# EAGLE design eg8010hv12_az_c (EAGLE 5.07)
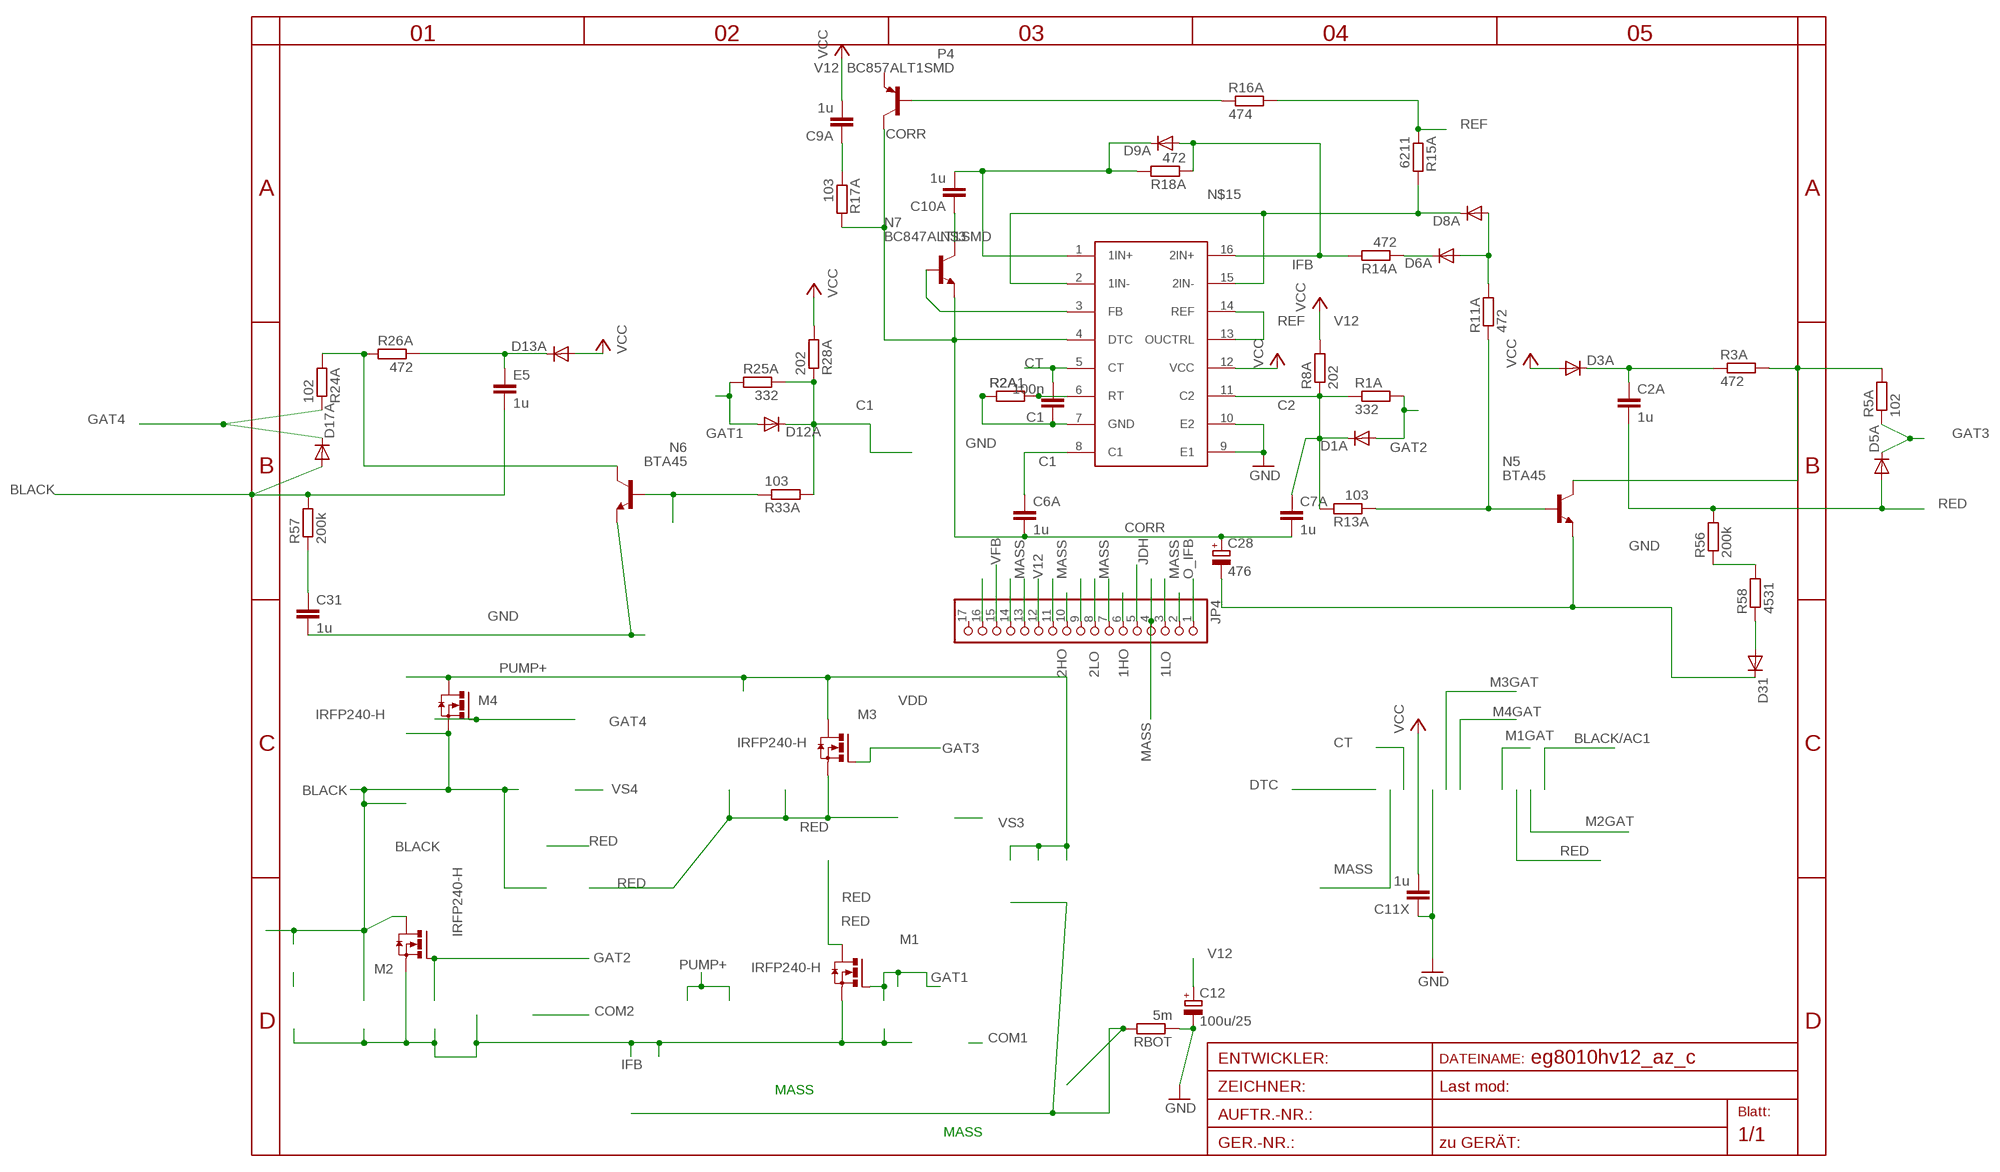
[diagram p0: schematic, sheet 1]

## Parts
C1  100n  C-EUC0805  [C0805]
C2A  1u  C-EUC1206  [C1206]
C6A  1u  C-EUC0805  [C0805]
C7A  1u  C-EUC0805  [C0805]
C9A  1u  C-EUC0805  [C0805]
C10A  1u  C-EUC1206  [C1206]
C11X  1u  C-EUC1206  [C1206]
C12  100u/25  CPOL-EUD  [PANASONIC_D]
C28  476  CPOL-EUD  [PANASONIC_D]
C31  1u  C-EUC1206  [C1206]
D1A  DIODE-MINIMELF  [MINIMELF]
D3A  DIODE-SMA-DO214  [SMA-DO214AC]
D5A  DIODE-MINIMELF  [MINIMELF]
D6A  DIODE-MINIMELF  [MINIMELF]
D8A  DIODE-MINIMELF  [MINIMELF]
D9A  DIODE-MINIMELF  [MINIMELF]
D12A  DIODE-MINIMELF  [MINIMELF]
D13A  DIODE-SMA-DO214  [SMA-DO214AC]
D17A  DIODE-MINIMELF  [MINIMELF]
D31  DIODE-MINIMELF  [MINIMELF]
E5  1u  C-EUC1206  [C1206]
JP4  PINHD-1X17  [1X17]
M1  IRFP240-H  [TO247BH]
M2  IRFP240-H  [TO247BH]
M3  IRFP240-H  [TO247BH]
M4  IRFP240-H  [TO247BH]
N5  BTA45  SMBTA45HV  [SOT23HV]
N6  BTA45  SMBTA45HV  [SOT23HV]
N7  BC847ALT1SMD  [SOT23]
P4  BC857ALT1SMD  [SOT23-BEC]
R1A  332  R-EU_R0805  [R0805]
R2A  R-EU_R0805  [R0805]
R2A1  R-EU_R0805  [R0805]
R3A  472  R-EU_R0805  [R0805]
R5A  102  R-EU_R1206  [R1206]
R8A  202  R-EU_R0805  [R0805]
R11A  472  R-EU_R0805  [R0805]
R13A  103  R-EU_R0805  [R0805]
R14A  472  R-EU_R0805  [R0805]
R15A  6211  R-EU_R1206  [R1206]
R16A  474  R-EU_R1206  [R1206]
R17A  103  R-EU_R1206  [R1206]
R18A  472  R-EU_R0805  [R0805]
R24A  102  R-EU_R1206  [R1206]
R25A  332  R-EU_R0805  [R0805]
R26A  472  R-EU_R0805  [R0805]
R28A  202  R-EU_R0805  [R0805]
R33A  103  R-EU_R0805  [R0805]
R56  200k  R-EU_R0805  [R0805]
R57  200k  R-EU_R0805  [R0805]
R58  4531  R-EU_R0805  [R0805]
RBOT  5m  R-EU_0204/7  [0204/7]
U$5  AZ7500SO16  [SO16]

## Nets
1HO: JP4.6
1LO: JP4.3
2HO: JP4.10
2LO: JP4.8
BLACK: D17A.A E5.2 M2.D M4.S R57.2
C1: C6A.1 D12A.C R25A.1 R28A.1 R33A.2 U$5.8(C1)
C2: C7A.1 D1A.C R1A.1 R8A.1 R13A.2 U$5.11(C2)
CORR: C6A.2 C7A.2 C28.+ N7.2(E) P4.C R17A.2 U$5.4(DTC)
CT: C1.2 U$5.5(CT)
DFG1: JP4.9
GAT1: D12A.A M1.G R25A.2
GAT2: D1A.A M2.G R1A.2
GAT3: D5A.C M3.G R5A.1
GAT4: D17A.C M4.G R24A.1
GND: C1.1 C11X.1 C12.- C28.- C31.2 D31.C N5.2(E) N6.2(E) R2A1.1 R2A.1 RBOT.1 U$5.7(GND) U$5.9(E1) U$5.10(E2)
IFB: D9A.A M1.S M2.S R14A.2 R18A.1 U$5.16(2IN+)
JDH: JP4.5
MASS: JP4.2 JP4.4 JP4.7 JP4.11 JP4.13 RBOT.2
N$3: C10A.2 D9A.C R18A.2 U$5.1(1IN+)
N$4: C2A.1 D3A.K(C) R3A.1
N$5: N5.3(C) R3A.2 R5A.2
N$11: N5.1(B) R11A.1 R13A.1
N$13: D6A.A D8A.A R11A.2
N$15: D8A.C R15A.2 U$5.2(1IN-) U$5.15(2IN-)
N$36: D6A.C R14A.1
N$37: P4.B R16A.1
N$38: R2A1.2 R2A.2 U$5.6(RT)
N$39: C9A.1 R17A.1
N$40: N7.1(B) U$5.3(FB)
N$41: C10A.1 N7.3(C)
N$42: D13A.K(C) E5.1 R26A.1
N$43: N6.3(C) R24A.2 R26A.2
N$44: N6.1(B) R33A.1
N$45: C31.1 R57.1
N$46: R56.1 R58.2
N$47: D31.A R58.1
O_IFB: JP4.1
PUMP+: M3.D M4.D
RED: C2A.2 D5A.A M1.D M3.S R56.2
REF: R15A.1 R16A.2 U$5.13(OUCTRL) U$5.14(REF)
TFB: JP4.16
V12: C9A.2 C11X.2 C12.+ D3A.A D13A.A JP4.12 R8A.2 R28A.2 U$5.12(VCC) ; supply symbol labelled VCC
VDD: JP4.14
VFB: JP4.15
Unconnected: JP4.17 P4.E

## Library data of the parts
C1 C2A C6A C7A C9A C10A C11X C31 E5 = rcl:C-EU: CAPACITOR, European symbol
C12 C28 = rcl:CPOL-EU: POLARIZED CAPACITOR, European symbol
D1A D3A D5A D6A D8A D9A D12A D13A D17A D31 = diode:DIODE-: DIODE
JP4 = pinhead:PINHD-1X17: PIN HEADER
M1-M4 = transistor-power:IRFP240: HEXFET Power MosFet Source: http://www.irf.com/
N5 N6 = transistor-npn:SMBTA45
N7 = transistor-npn:BC847*: NPN Transistor
P4 = transistor-pnp:BC857*: PNP Transistror
R1A R2A R2A1 R3A R5A R8A R11A R13A R14A R15A R16A R17A R18A R24A R25A R26A R28A R33A R56-R58 RBOT = rcl:R-EU_: RESISTOR, European symbol
U$5 = az7500:AZ7500

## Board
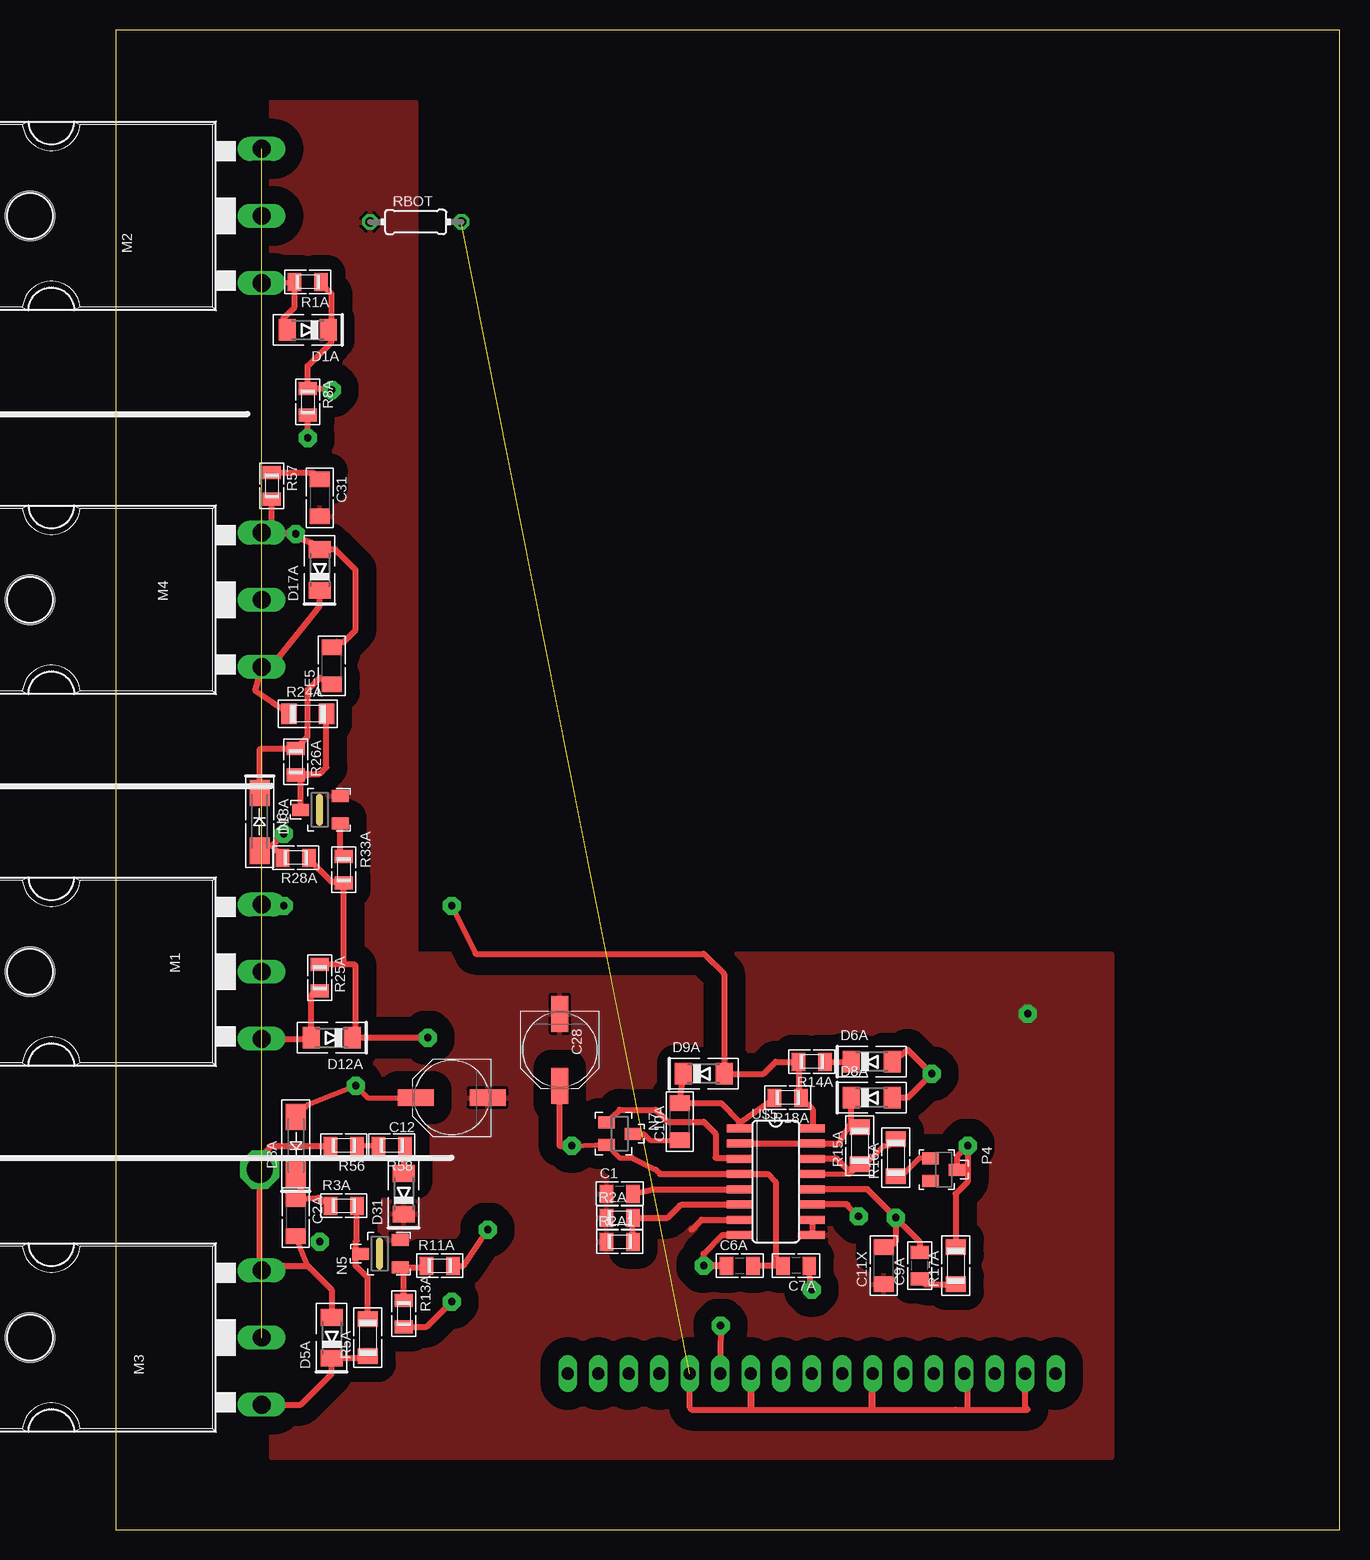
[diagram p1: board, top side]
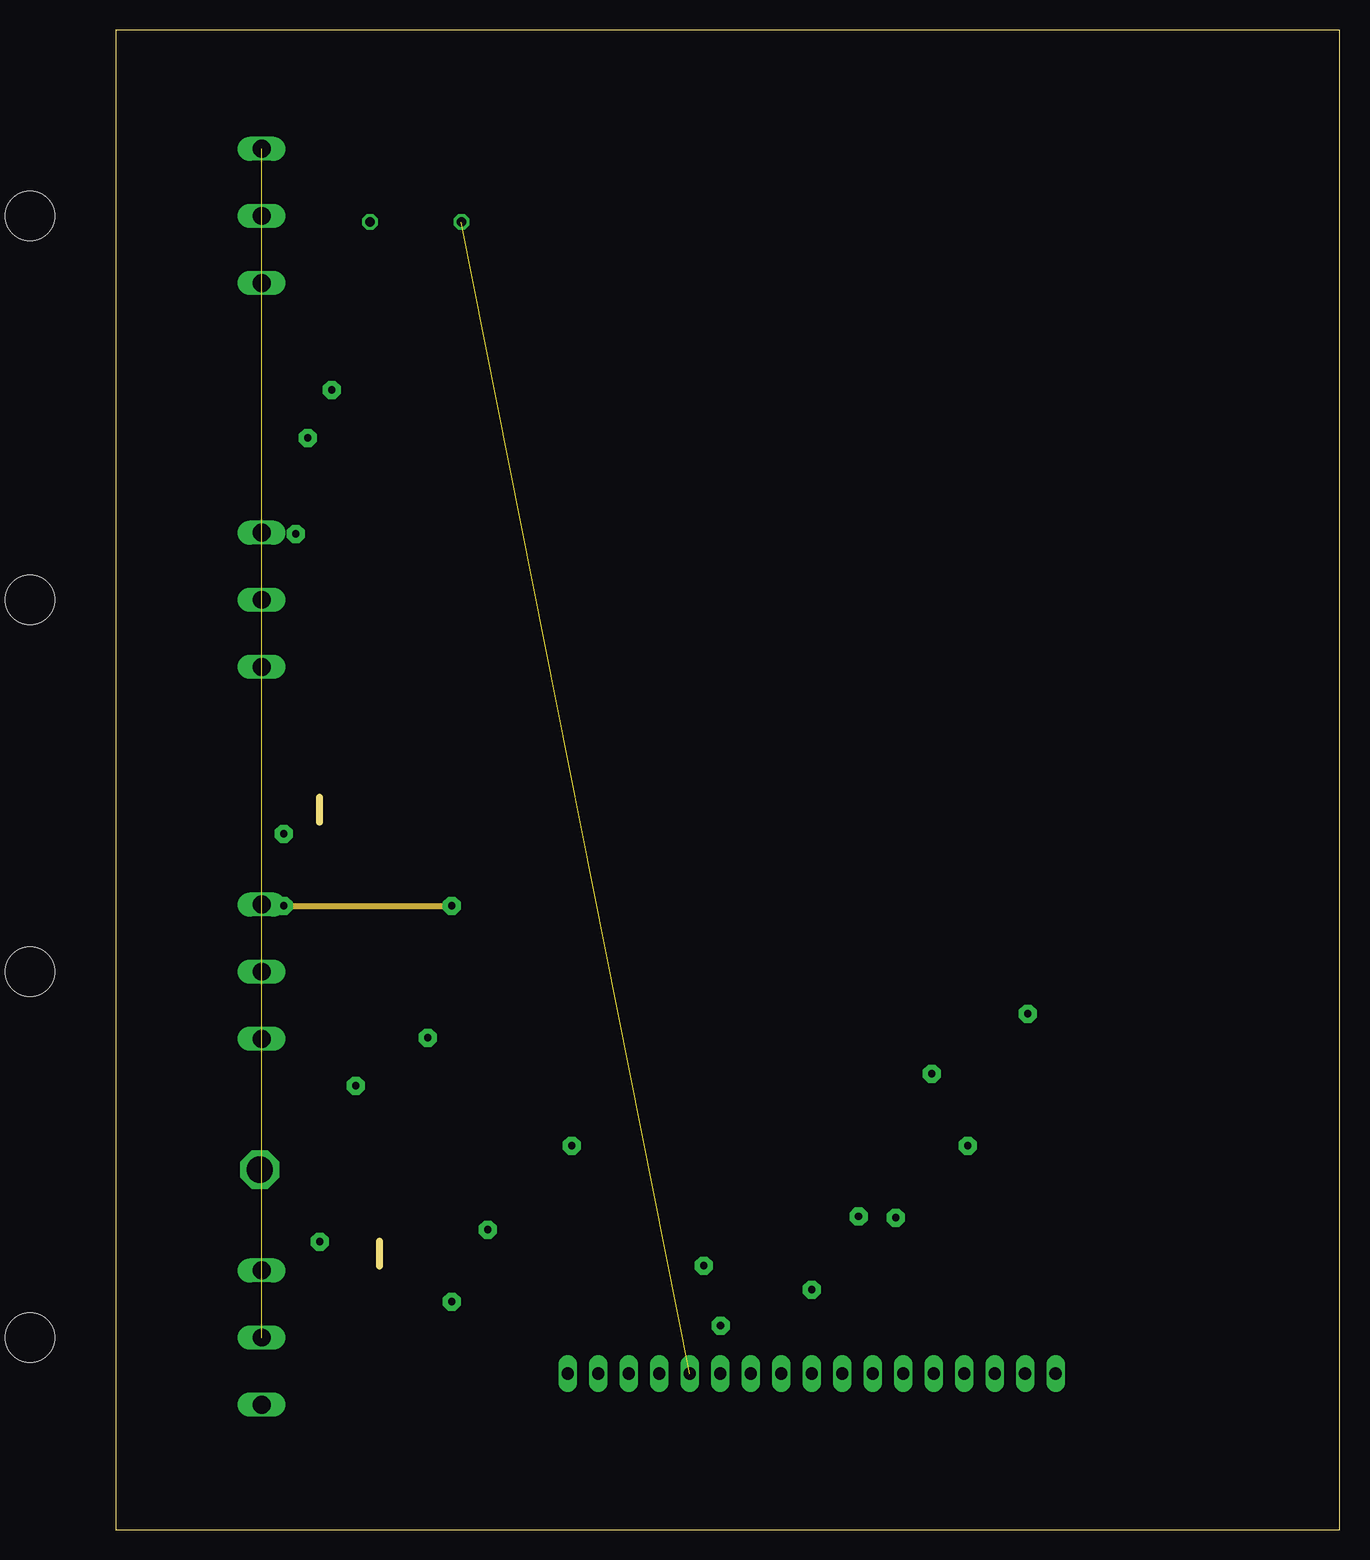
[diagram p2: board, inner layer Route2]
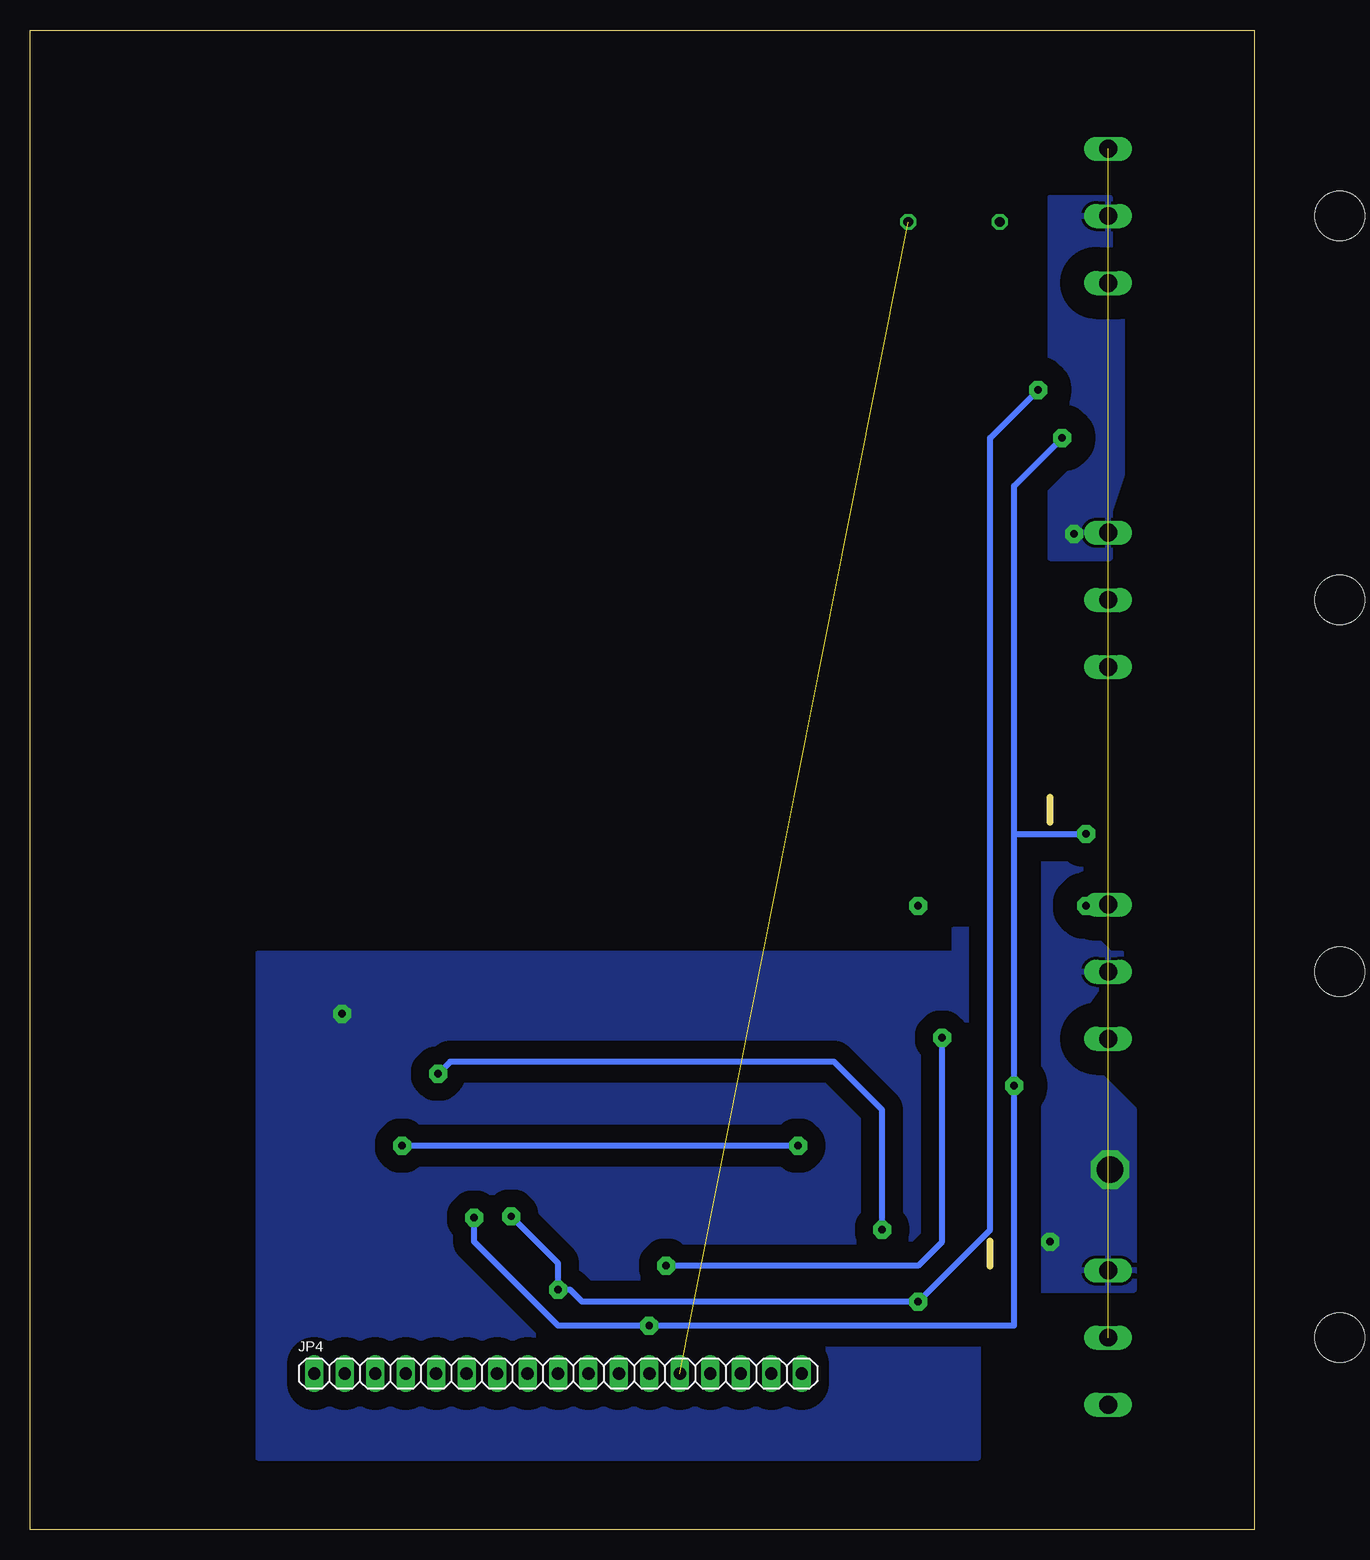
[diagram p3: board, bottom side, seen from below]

Size 102 x 125 mm. Coordinates in mm from the lower left corner, seen from the top.
Outline: 0,0 102,0 102,125 0,125 0,0
Copper layers (1*16): Top 0.035mm / dielectric 1.5mm / Bottom 0.035mm
Design rules "default *": minimum track width 10mil, minimum drill 20mil, track to track 8mil, track to pad 8mil, pad to pad 8mil, via to via 8mil, smd to smd 8mil, copper to edge 4mm, drill to drill 8mil, minimum pad ring 10mil, minimum via ring 8mil, stop-mask expansion 4mil, vias tented up to drill 0mil, thermal gap 10mil

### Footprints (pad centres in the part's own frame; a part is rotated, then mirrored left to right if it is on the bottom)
C0805 = smd 1.1 x 1.5: 1 -1.1,0; 2 1.1,0
C1206 = smd 1.3 x 1.7: 1 -1.55,0; 2 1.55,0
PANASONIC_D = smd 3 x 1.4: + 3,0; - -3,0
MINIMELF = smd 1.4 x 1.8: A 1.7,0; C -1.7,0
SMA-DO214AC = smd 2.2 x 1.7: A 2.4,0; K -2.4,0
1X17 = drill 1.016 long: 1 -20.32,0; 2 -17.78,0; 3 -15.24,0; 4 -12.7,0; 5 -10.16,0; 6 -7.62,0; 7 -5.08,0; 8 -2.54,0; 9 0,0; 10 2.54,0; 11 5.08,0; 12 7.62,0; 13 10.16,0; 14 12.7,0; 15 15.24,0; 16 17.78,0; 17 20.32,0
TO247BH = drill 1.499 long: D 0,-10.16; G -5.588,-10.16; S 5.588,-10.16 | hole 4.115: 0,9.144
SOT23HV = smd 1 x 1.4: 1 -1.15,-1.7; 2 1.15,-1.7; 3 0,1.6
SOT23 = smd 1 x 1.4: 1 -0.95,-1.1; 2 0.95,-1.1; 3 0,1.1
SOT23-BEC = smd 1 x 1.4: B -0.95,-1.1; C 0,1.1; E 0.95,-1.1
R0805 = smd 1.1 x 1.5: 1 -1.1,0; 2 1.1,0
R1206 = smd 1.3 x 1.7: 1 -1.55,0; 2 1.55,0
0204/7 = drill 0.813 octagon: 1 -3.81,0; 2 3.81,0
SO16 = smd 2.032 x 0.66: 1 -3.073,4.445; 2 -3.073,3.175; 3 -3.073,1.905; 4 -3.073,0.635; 5 -3.073,-0.635; 6 -3.073,-1.905; 7 -3.073,-3.175; 8 -3.073,-4.445; 9 3.073,-4.445; 10 3.073,-3.175; 11 3.073,-1.905; 12 3.073,-0.635; 13 3.073,0.635; 14 3.073,1.905; 15 3.073,3.175; 16 3.073,4.445

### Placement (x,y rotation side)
C1  42,28 0 top
C2A  15,26 270 top
C6A  52,22 0 top
C7A  56.7,22 180 top
C9A  67,22 90 top
C10A  47,34 90 top
C11X  64,22 90 top
C12  28,36 180 top
C28  37,40 270 top
C31  17,86 270 top
D1A  16,100 180 top
D3A  15,32 90 top
D5A  18,16 90 top
D6A  63,39 0 top
D8A  63,36 0 top
D9A  49,38 0 top
D12A  18,41 180 top
D13A  12,59 270 top
D17A  17,80 90 top
D31  24,28 90 top
E5  18,72 90 top
JP4  58,13 0 bottom
M1  2,46.5 90 top
M2  2,109.5 90 top
M3  2,16 90 top
M4  2,77.5 90 top
N5  22,23 90 top
N6  17,60 90 top
N7  42,33 270 top
P4  69,30 270 top
R1A  16,104 180 top
R2A  42,26 0 top
R2A1  42,24 0 top
R3A  19,27 0 top
R5A  21,16 90 top
R8A  16,94 270 top
R11A  27,22 0 top
R13A  24,18 270 top
R14A  58,39 180 top
R15A  62,32 90 top
R16A  65,31 90 top
R17A  70,22 90 top
R18A  56,36 180 top
R24A  16,68 0 top
R25A  17,46 270 top
R26A  15,64 270 top
R28A  15,56 180 top
R33A  19,55 270 top
R56  19,32 180 top
R57  13,87 270 top
R58  23,32 180 top
RBOT  25,109 0 top
U$5  55,29 0 top

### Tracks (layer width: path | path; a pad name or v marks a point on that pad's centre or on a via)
BLACK  (via drill 0.6 pad 1.5)
  Top 0.5: M4.S 13.91,83.09 17,82 D17A.A 18.3,81.7 20,80 20,75 19,74 18.45,74 E5.2 | R57.2 13,83.93 M4.S | M4.S 12.07,83
  other vias: 15,83
  pour Bottom (isolate 2): 12,111 17,111 17,81 12,81 12,85 11,88 11,105 13,107 12,107
C1  (via drill 0.6 pad 1.5)
  Top 0.5: 19,47.1 19.9,47.1 20,47 20,41.3 D12A.C v26,41 | 19,47.1 R25A.1 | U$5.8 50.56,24.55 49,23 49,22.1 C6A.1 v49,22 | 19,47.1 R33A.2 18.9,54 18,54 16.1,55.9 R28A.1
  Bottom 0.5: v26,41 26,24 28,22 v49,22
C2  (via drill 0.6 pad 1.5)
  Top 0.5: R1A.1 17.1,103.9 18,103 18,100.3 D1A.C 18,99.7 18,99 16,97 R8A.1 16.9,95.1 v18,95 | R13A.2 25.9,16.9 v28,19 | v61.91,26.09 61,27 61,27.09 U$5.11 | v58,20 57.9,20 C7A.1
  Bottom 0.5: v18,95 22,91 22,25 v28,19 56,19 57,20 v58,20 58,22.19 v61.91,26.09
CORR  (via drill 0.6 pad 1.5)
  Top 0.406: v38,32 40,32.05 N7.2 41.95,31 43,31
  Top 0.5: 43,31 45,30 45.36,29.64 U$5.4 54.37,29.64 55,29 55,22.1 C7A.2 C6A.2 | v38,32 37,32 C28.+ | P4.C 70.1,31.1 v71,32 71,29 70,28 R17A.2
  Bottom 0.5: v38,32 54,32 v71,32
CT
  Top 0.5: U$5.5 44.73,28.36 C1.2
GAT1
  Top 0.5: M1.G 16.21,40.91 D12A.A 16.3,44.6 R25A.2
GAT2
  Top 0.406: M2.G 14.9,103.91 R1A.2
  Top 0.5: R1A.2 14.9,101.9 14,101 14,100.3 D1A.A
GAT3
  Top 0.5: M3.G 15.41,10.41 18,13 D5A.C 20.85,14.3 R5A.1
GAT4
  Top 0.5: R24A.1 11.64,69.91 M4.G 12.25,72 13,72 17,77 D17A.C
GND  (via drill 0.6 pad 1.5)
  Top 0.5: U$5.7 48.83,25.82 48,25 | U$5.9 U$5.10
  other vias: 76,43
  pour Top (isolate 1.5): 13,119 25,119 25,48 83,48 83,6 13,6
  pour Bottom (isolate 1.5): 23,50 25,50 25,48 83,48 83,6 23,6
IFB  (via drill 0.6 pad 1.5)  (1 unrouted)
  Top 0.5: v28,52 30,48 49,48 50.7,46.3 D9A.A 54,38 55,39 R14A.2 56.9,36.2 R18A.1 58.07,35.03 U$5.16 | v14,52 12.25,52 M1.S
  Route2 0.5: v14,52 v28,52
MASS  (1 unrouted)
  Top 0.5: JP4.13 47.84,10.16 48,10 53,10 | 53,10 53,12.92 JP4.11 52.92,10.08 53,10 | 53,10 63,10 | 63,10 63,12.92 JP4.7 63.08,10.08 63,10 | 63,10 70,10 71,10 | 71,10 71,12.7 JP4.4 | JP4.2 75.78,10.22 76,10 71,10
N$3
  Top 0.5: D9A.C 47.3,37.8 C10A.2 50.45,35.55 52.05,33.95 | U$5.1 51.93,33.83 52.05,33.95 | 52.05,33.95 R18A.2
N$4
  Top 0.5: R3A.1 16.9,27.65 C2A.1 15.55,28.05 D3A.K
N$5
  Top 0.5: R5A.2 21,21 20,22 20,22.6 N5.3 20,23.4 20,24 20.1,24.1 R3A.2
N$11
  Top 0.5: R13A.1 24,21.55 N5.1 25.75,21.85 R11A.1
N$13  (via drill 0.6 pad 1.5)
  Top 0.5: R11A.2 29,22 v31,25 | D8A.A 66,36 v68,38 66,40 D6A.A
  Bottom 0.5: v31,25 31,35 35,39 67,39 v68,38
N$15
  Top 0.5: U$5.2 U$5.15 60.28,32.17 61.28,33.98 | 61.28,33.98 D8A.C | R15A.2 61.7,33.55 61.28,33.98
N$36
  Top 0.5: R14A.1 D6A.C
N$37
  Top 0.406: R16A.1 65.45,29.45 67,31 67.85,31 P4.B 67.95,30.95 68,31
N$38
  Top 0.5: U$5.6 47.19,27.09 47,27 46,26 R2A.2 R2A1.2
N$39
  Top 0.5: R17A.1 67.45,20.45 C9A.1
N$40
  Top 0.5: N7.1 42,34.95 42,35 45,35 46,34 49,34 50,33 50,31 51.83,31 U$5.3
N$41
  Top 0.406: C10A.1 44.55,32.45 44,33 N7.3
N$42
  Top 0.5: E5.1 17,71 16,70 16,66.1 R26A.1 12.1,65.1 12,65 D13A.K
N$43
  Top 0.5: N6.3 15.4,62.5 | 15.4,62.5 R26A.2 | R24A.2 17.55,63.55 17,63 15.9,63 15.4,62.5
N$44
  Top 0.5: N6.1 18.7,56.4 R33A.1
N$45
  Top 0.5: R57.1 16.45,88.1 C31.1
N$46
  Top 0.406: R58.2 R56.1
N$47
  Top 0.406: D31.A 24,31.9 R58.1
PUMP+  (1 unrouted)
RED  (via drill 0.6 pad 1.5, 2.2 pad 1.5)
  Top 0.406: M3.S 12.16,22.16 16,22 C2A.2
  Top 0.5: D5A.A 18,20 16,22 12.57,22 M3.S | R56.2 13,32 12,31 12,22.32 12.16,22.16
  other vias: 12,30 17,24
  pour Bottom (isolate 2): 11,60 17,60 18,58 18,20 10,20 10,35 16,41 11,48 12,48 16,52 11,55
REF
  Top 0.406: U$5.13 61.19,29.64 R15A.1 62.45,30.45 64,32 64.45,32 R16A.2
  Top 0.5: U$5.14 60.09,30.91 61,30 61.55,30 R15A.1
V12  (via drill 0.6 pad 1.5)
  Top 0.406: C12.+ 21,36 v20,37 16,35.4 D3A.A
  Top 0.5: JP4.12 50.38,14.62 v50.4,17 | v16,91 R8A.2 | U$5.12 62.63,28.36 v65,26 | R28A.2 13.9,56.1 13,57 | 13,57 12.4,57 D13A.A | C11X.2 64.55,23.55 65,24 v65,26 | C9A.2 67,24 v65,26 | v14,58 13,57
  Bottom 0.5: 20,58 20,87 v16,91 | v65,26 65,24 58,17 v50.4,17 20,17 v20,37 20,58 | 20,58 v14,58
